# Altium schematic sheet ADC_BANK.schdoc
size 297 x 209 mm; Symbol: Drawing-Symbol_A4; @Project Name: Inverted_MAML_6x6; @Page Count: 1; @Update Date: 2026-06-14; @Create Date: 2026-06-14; @Schematic Name: Schematic1; @Page No: 1; @Page Name: P1; Company: EasyEDA.com; Version: V1.0; Page Size: A4; Device: Drawing-Symbol_A4; @Create Time: 19:04:35; @Update Time: 19:04:35; Border: 1; Width: 1170; Height: 825; Region Start: 1; X Region Count: 6; Y Region Count: 4; Blade Width: 10; Title Block Position: 3
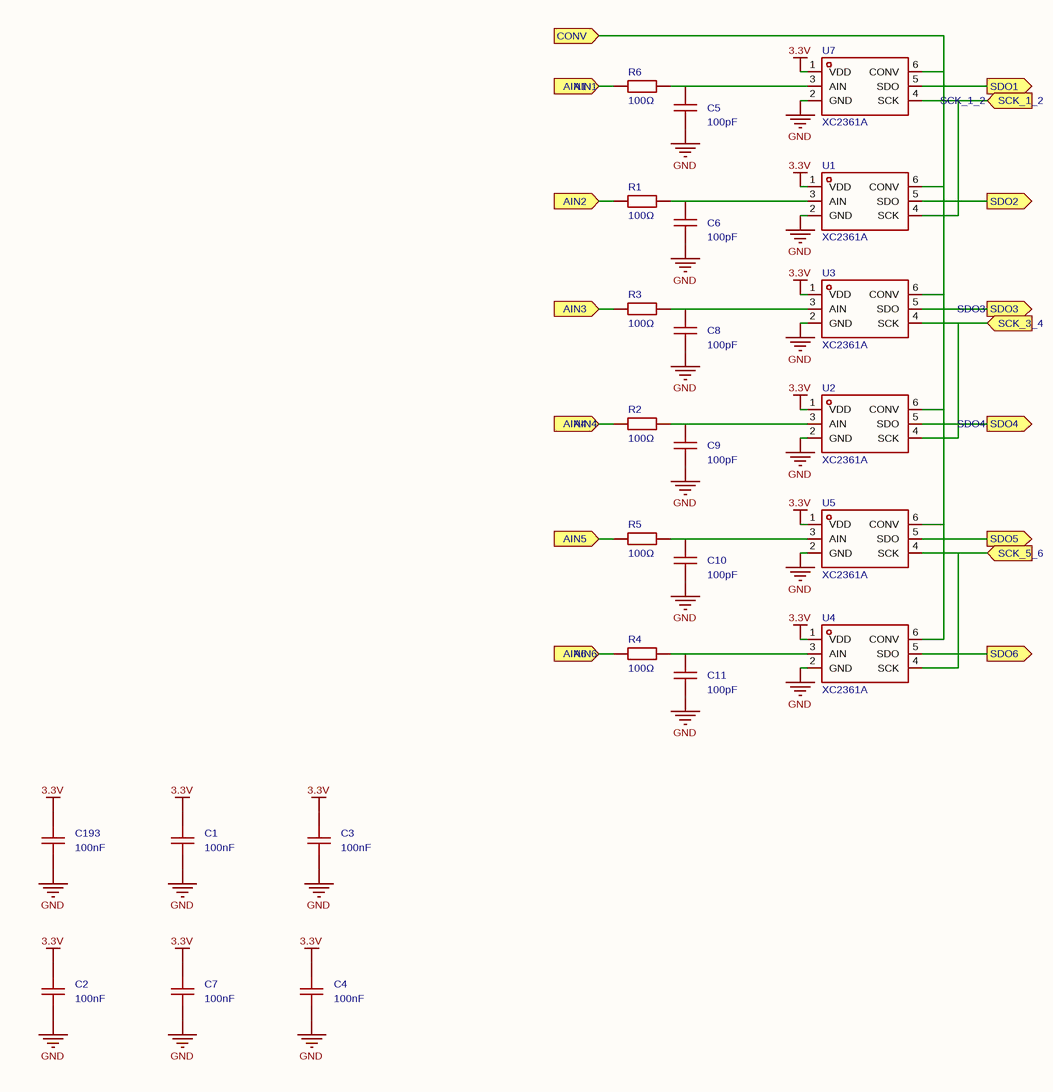
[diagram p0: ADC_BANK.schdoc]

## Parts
C1  100nF  [C0402]
C2  100nF  [C0402]
C3  100nF  [C0402]
C4  100nF  [C0402]
C5  100pF  [C0402]
C6  100pF  [C0402]
C7  100nF  [C0402]
C8  100pF  [C0402]
C9  100pF  [C0402]
C10  100pF  [C0402]
C11  100pF  [C0402]
C193  100nF  [C0402]
R1  100Ω  [R0402]
R2  100Ω  [R0402]
R3  100Ω  [R0402]
R4  100Ω  [R0402]
R5  100Ω  [R0402]
R6  100Ω  [R0402]
U1  XC2361A  [TSOT-23-6_L2.9-W1.6-P0.95-LS2.6-BL]
U2  XC2361A  [TSOT-23-6_L2.9-W1.6-P0.95-LS2.6-BL]
U3  XC2361A  [TSOT-23-6_L2.9-W1.6-P0.95-LS2.6-BL]
U4  XC2361A  [TSOT-23-6_L2.9-W1.6-P0.95-LS2.6-BL]
U5  XC2361A  [TSOT-23-6_L2.9-W1.6-P0.95-LS2.6-BL]
U7  XC2361A  [TSOT-23-6_L2.9-W1.6-P0.95-LS2.6-BL]

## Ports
AIN1 (in), AIN2 (in), AIN3 (in), AIN4 (in), AIN5 (in), AIN6 (in), CONV (in), SCK_1_2 (in), SCK_3_4 (in), SCK_5_6 (in), SDO1 (out), SDO2 (out), SDO3 (out), SDO4 (out), SDO5 (out), SDO6 (out)

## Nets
3.3V: C1.2 C2.2 C3.2 C4.2 C7.2 C193.2 U1.1(VDD) U2.1(VDD) U3.1(VDD) U4.1(VDD) U5.1(VDD) U7.1(VDD)
GND: C1.1 C2.1 C3.1 C4.1 C5.1 C6.1 C7.1 C8.1 C9.1 C10.1 C11.1 C193.1 U1.2(GND) U2.2(GND) U3.2(GND) U4.2(GND) U5.2(GND) U7.2(GND)
AIN1: R6.2 ; port AIN1
AIN2: R1.2 ; port AIN2
AIN3: R3.2 ; port AIN3
AIN4: R2.2 ; port AIN4
AIN5: R5.2 ; port AIN5
AIN6: R4.2 ; port AIN6
CONV: U1.6(CONV) U2.6(CONV) U3.6(CONV) U4.6(CONV) U5.6(CONV) U7.6(CONV) ; port CONV
SCK_1_2: U1.4(SCK) U7.4(SCK) ; port SCK_1_2
SCK_3_4: U2.4(SCK) U3.4(SCK) ; port SCK_3_4
SCK_5_6: U4.4(SCK) U5.4(SCK) ; port SCK_5_6
SDO1: U7.5(SDO) ; port SDO1
SDO2: U1.5(SDO) ; port SDO2
SDO3: U3.5(SDO) ; port SDO3
SDO4: U2.5(SDO) ; port SDO4
SDO5: U5.5(SDO) ; port SDO5
SDO6: U4.5(SDO) ; port SDO6
NetC5_2: C5.2 R6.1 U7.3(AIN)
NetC6_2: C6.2 R1.1 U1.3(AIN)
NetC8_2: C8.2 R3.1 U3.3(AIN)
NetC9_2: C9.2 R2.1 U2.3(AIN)
NetC10_2: C10.2 R5.1 U5.3(AIN)
NetC11_2: C11.2 R4.1 U4.3(AIN)

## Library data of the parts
C1-C4 C7 C193 = CL05B104KO5NNNC: Capacitance:100nF Tolerance:±10% Tolerance:±10% Voltage Rating:16V Temperature Coefficient:X7R; Manufacturer: SAMSUNG(三星); 3D Model: b7d13df3e9464d7a99d0651d1a5b4d570819f05c4eef4c71ace90d822a990e87; 3D Model Transform: 39.37,19.685,0,0,0,0,0,0,0; Tolerance: ±10%; Voltage Rating: 16V; Temperature Coefficient: X7R; AddInBom: yes; ModelName: C0402_L1.0-W0.5-H0.5
C5 C6 C8-C11 = 0402CG101J500NT: Capacitance:100pF Tolerance:±5% Tolerance:±5% Voltage Rating:50V Temperature Coefficient:C0G; Manufacturer: FH(风华); Add into BOM: yes; 3D Model: b7d13df3e9464d7a99d0651d1a5b4d57; 3D Model Transform: 39.37,19.685,0,0,0,0,0,0,0; Tolerance: ±5%; Voltage Rating: 50V; Temperature Coefficient: C0G; ModelName: C0402_L1.0-W0.5-H0.5
R1-R6 = 0402WGF1000TCE: Type:Thick Film Resistors Resistance: Tolerance:±1% Tolerance:±1% Power(Watts): Overload Voltage (Max): Temperature Coefficient:±200ppm/℃ Temperature Coefficient:±200ppm/℃ Operating Temperature Range:-55℃~+155℃ Operating Temperature Range:-55℃~+155℃; Manufacturer: UNI-ROYAL(厚声); 3D Model: efdecb7dae4442949d28eecaf748420f0819f05c4eef4c71ace90d822a990e87; 3D Model Transform: 39.37,19.685,0,0,0,0,0,0,0; Tolerance: ±1%; AddInBom: yes; ModelName: R0402_L1.0-W0.5-H0.4
U1-U5 U7 = XC2361A: Resolution (Bits):12 Sampling Rate:1MHz number of channels:1 Voltage - Supply:3.3V~4.8V Voltage - Supply:3.3V~4.8V Interface:SPI differential input:No Integral non - linearity:1.5LSB Integral non - linearity:1.5LSB Operating Temperature:-40℃~+85℃ Operatin; Manufacturer: SiChange(芯昌科技); 3D Model: 797404eaec294817ba12cab286659b7a; 3D Model Transform: 114.173,110.236,0,0,0,0,0,0,0; Resolution (Bits): 12; Sampling Rate: 1MHz; number of channels: 1; Interface: SPI; differential input: No; Integral non - linearity: 1.5LSB; Signal-to-Noise Ratio: 72.4dB; Clock Frequency: 20MHz; ADC architecture: SAR; Quiescent Current (Iq): 1.56mA; AddInBom: yes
